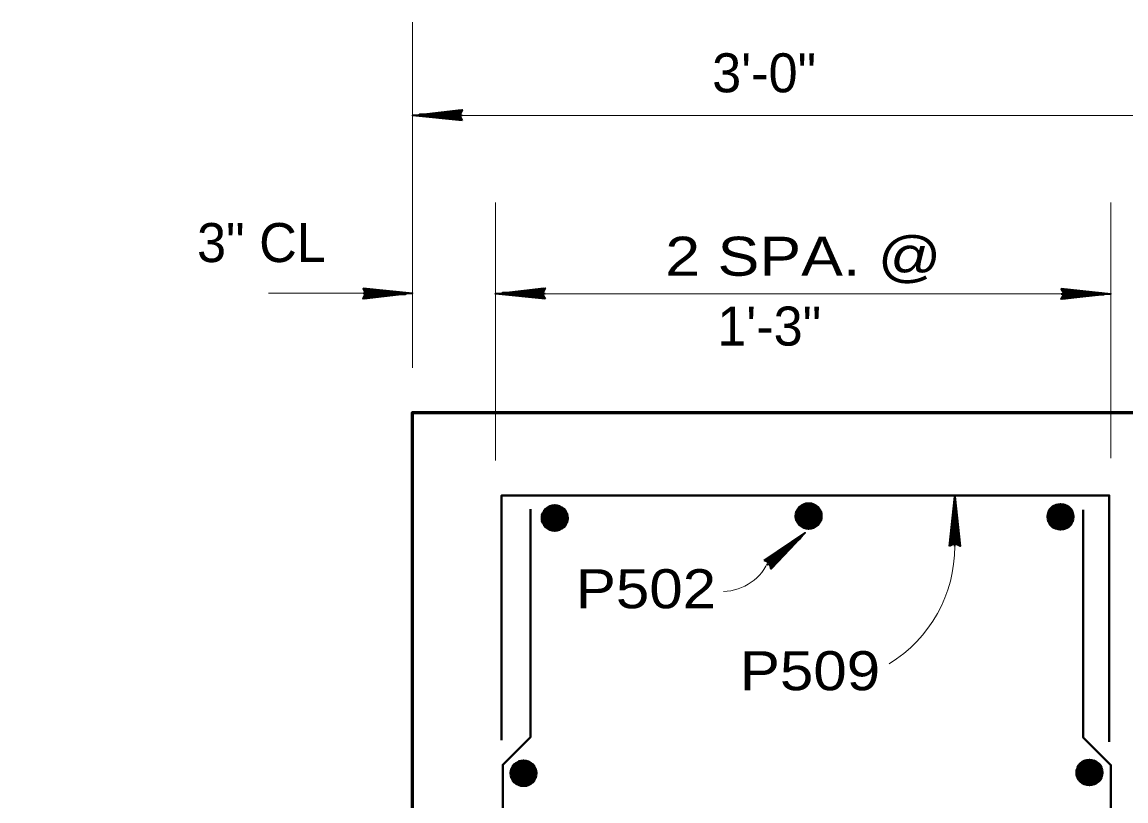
# Model space of a CAD drawing. Extents: x 3.64 to 6.84, y -0.8 to 1.19.
# Drawn here: x 5.0189 to 5.2545, y 0.1917 to 0.358 of the extents above; entities that cross this region are included whole.
import ezdxf

# ---------------------------------------------------------------- set-up
doc = ezdxf.new("R2010")
doc.units = 0
doc.header["$LTSCALE"] = 0.0033
doc.layers.add('1', color=7, linetype='Continuous', lineweight=40)

msp = doc.modelspace()

# ---------------------------------------------------------------- linework, layer by layer
at = {"layer": '1', "lineweight": 13}
for p, q in [((5.10225, 0.284167), (5.10225, 0.358)), ((5.1025, 0.338083), (5.268917, 0.338083)), ((5.119917, 0.264417), (5.119917, 0.3195)), ((5.25125, 0.264917), (5.25125, 0.3195)), ((5.0715, 0.300083), (5.092333, 0.300083)), ((5.11975, 0.3), (5.250667, 0.3))]:
    msp.add_line(p, q, dxfattribs=at)
at = {"layer": '1', "lineweight": 35}
for p, q in [((5.112833, 0.338083), (5.10225, 0.338083)), ((5.112583, 0.33725), (5.10475, 0.33825)), ((5.112583, 0.33725), (5.10475, 0.338083)), ((5.112583, 0.337083), (5.10475, 0.338)), ((5.112583, 0.337083), (5.10475, 0.338)), ((5.112583, 0.337167), (5.10475, 0.338)), ((5.112583, 0.339167), (5.10525, 0.338333)), ((5.112583, 0.339), (5.10525, 0.33825)), ((5.112583, 0.338917), (5.10525, 0.338083)), ((5.112667, 0.33875), (5.105333, 0.338)), ((5.091667, 0.300083), (5.10225, 0.300083)), ((5.091833, 0.299417), (5.099167, 0.300167)), ((5.091917, 0.301083), (5.09975, 0.300167)), ((5.091917, 0.301083), (5.09975, 0.300167)), ((5.091917, 0.301), (5.09975, 0.300167)), ((5.091917, 0.300917), (5.09975, 0.300083)), ((5.091917, 0.300917), (5.09975, 0.299917)), ((5.091917, 0.29925), (5.09925, 0.300083)), ((5.091917, 0.299167), (5.09925, 0.299917)), ((5.091917, 0.299), (5.09925, 0.299833)), ((5.1305, 0.3), (5.119917, 0.3)), ((5.13025, 0.299167), (5.122417, 0.300167)), ((5.13025, 0.299167), (5.122417, 0.3)), ((5.13025, 0.299), (5.122417, 0.299917)), ((5.13025, 0.299), (5.122417, 0.299917)), ((5.13025, 0.299083), (5.122417, 0.299917)), ((5.13025, 0.301083), (5.122917, 0.30025)), ((5.13025, 0.300917), (5.122917, 0.300167)), ((5.13025, 0.300833), (5.122917, 0.3)), ((5.130333, 0.300667), (5.123, 0.299917)), ((5.240667, 0.3), (5.25125, 0.3)), ((5.240833, 0.299333), (5.248167, 0.300083)), ((5.240917, 0.301), (5.24875, 0.300083)), ((5.240917, 0.301), (5.24875, 0.300083)), ((5.240917, 0.300917), (5.24875, 0.300083)), ((5.240917, 0.300833), (5.24875, 0.3)), ((5.240917, 0.300833), (5.24875, 0.299833)), ((5.240917, 0.299167), (5.24825, 0.3)), ((5.240917, 0.299083), (5.24825, 0.299833)), ((5.240917, 0.298917), (5.24825, 0.29975)), ((5.217917, 0.246083), (5.217917, 0.256667)), ((5.216917, 0.246333), (5.217833, 0.254167)), ((5.216917, 0.246333), (5.217833, 0.254167)), ((5.217, 0.246333), (5.217833, 0.254167)), ((5.217083, 0.246333), (5.217917, 0.254167)), ((5.217083, 0.246333), (5.218083, 0.254167)), ((5.218583, 0.24625), (5.217833, 0.253583)), ((5.21875, 0.246333), (5.217917, 0.253667)), ((5.218833, 0.246333), (5.218083, 0.253667)), ((5.219, 0.246333), (5.218167, 0.253667)), ((5.177583, 0.242917), (5.184167, 0.247417)), ((5.177583, 0.242917), (5.184167, 0.247417)), ((5.177667, 0.242917), (5.184167, 0.247417)), ((5.178, 0.242), (5.186, 0.248917)), ((5.17775, 0.242917), (5.18425, 0.24725)), ((5.17775, 0.242917), (5.18425, 0.247167)), ((5.178583, 0.24175), (5.183667, 0.246917)), ((5.17875, 0.2415), (5.183917, 0.246833)), ((5.178833, 0.241583), (5.183833, 0.247)), ((5.178917, 0.241417), (5.184, 0.246833))]:
    msp.add_line(p, q, dxfattribs=at)
at = {"layer": '1'}
for p, q in [((5.134917, 0.253333), (5.133667, 0.2545)), ((5.185083, 0.254417), (5.188917, 0.25375)), ((5.187, 0.253583), (5.188333, 0.254583)), ((5.189083, 0.25375), (5.187833, 0.254917)), ((5.24075, 0.253417), (5.242083, 0.254417)), ((5.242833, 0.253583), (5.241583, 0.25475)), ((5.1305, 0.253667), (5.135083, 0.2515)), ((5.130583, 0.25225), (5.134417, 0.2515)), ((5.130583, 0.252083), (5.134417, 0.251333)), ((5.130667, 0.252667), (5.1345, 0.252)), ((5.130667, 0.2525), (5.1345, 0.25175)), ((5.13075, 0.25325), (5.134667, 0.2525)), ((5.13075, 0.253083), (5.134667, 0.252333)), ((5.13075, 0.252833), (5.134583, 0.252083)), ((5.130833, 0.253667), (5.13475, 0.253)), ((5.130833, 0.2535), (5.13475, 0.25275)), ((5.130917, 0.254), (5.13475, 0.253333)), ((5.132833, 0.253167), (5.134167, 0.254167)), ((5.184667, 0.254083), (5.18925, 0.251917)), ((5.184667, 0.25225), (5.188583, 0.2515)), ((5.18475, 0.252667), (5.188583, 0.251917)), ((5.18475, 0.2525), (5.188583, 0.25175)), ((5.184833, 0.253083), (5.188667, 0.252417)), ((5.184833, 0.252917), (5.188667, 0.252167)), ((5.184917, 0.253667), (5.188833, 0.252917)), ((5.184917, 0.2535), (5.188833, 0.25275)), ((5.184917, 0.25325), (5.18875, 0.2525)), ((5.185, 0.254083), (5.188917, 0.253417)), ((5.185, 0.253917), (5.188917, 0.253167)), ((5.238417, 0.253917), (5.243, 0.25175)), ((5.238417, 0.252083), (5.242333, 0.251333)), ((5.2385, 0.2525), (5.242333, 0.25175)), ((5.2385, 0.252333), (5.242333, 0.251583)), ((5.238583, 0.252917), (5.242417, 0.25225)), ((5.238583, 0.25275), (5.242417, 0.252)), ((5.238667, 0.2535), (5.242583, 0.25275)), ((5.238667, 0.253333), (5.242583, 0.252583)), ((5.238667, 0.253083), (5.2425, 0.252333)), ((5.23875, 0.253917), (5.242667, 0.25325)), ((5.23875, 0.25375), (5.242667, 0.253)), ((5.238833, 0.25425), (5.242667, 0.253583)), ((5.130333, 0.250917), (5.134167, 0.250167)), ((5.130333, 0.25075), (5.134167, 0.25)), ((5.130417, 0.251417), (5.134333, 0.250667)), ((5.130417, 0.25125), (5.13425, 0.2505)), ((5.130417, 0.251), (5.13425, 0.250333)), ((5.1305, 0.251833), (5.134417, 0.251083)), ((5.134667, 0.2505), (5.130917, 0.250083)), ((5.1845, 0.251333), (5.188333, 0.250583)), ((5.1845, 0.251167), (5.188333, 0.250417)), ((5.184583, 0.251833), (5.1885, 0.251083)), ((5.184583, 0.251667), (5.188417, 0.250917)), ((5.184583, 0.251417), (5.188417, 0.25075)), ((5.188833, 0.250917), (5.185083, 0.2505)), ((5.23825, 0.251167), (5.242083, 0.250417)), ((5.23825, 0.251), (5.242083, 0.25025)), ((5.238333, 0.251667), (5.24225, 0.250917)), ((5.238333, 0.2515), (5.242167, 0.25075)), ((5.238333, 0.25125), (5.242167, 0.250583)), ((5.242583, 0.25075), (5.238833, 0.250333)), ((5.123833, 0.199167), (5.128417, 0.197)), ((5.124, 0.198167), (5.127833, 0.1975)), ((5.124, 0.198), (5.127833, 0.19725)), ((5.124083, 0.19875), (5.128, 0.198)), ((5.124083, 0.198583), (5.128, 0.197833)), ((5.124083, 0.198333), (5.127917, 0.197583)), ((5.124167, 0.199167), (5.128083, 0.1985)), ((5.124167, 0.199), (5.128083, 0.19825)), ((5.12425, 0.1995), (5.128083, 0.198833)), ((5.126167, 0.198667), (5.1275, 0.199667)), ((5.12825, 0.198833), (5.127, 0.2)), ((5.244583, 0.199333), (5.249167, 0.197167)), ((5.244667, 0.197917), (5.2485, 0.197167)), ((5.24475, 0.198333), (5.248583, 0.197667)), ((5.24475, 0.198167), (5.248583, 0.197417)), ((5.244833, 0.198917), (5.24875, 0.198167)), ((5.244833, 0.19875), (5.24875, 0.198)), ((5.244833, 0.1985), (5.248667, 0.19775)), ((5.244917, 0.199333), (5.248833, 0.198667)), ((5.244917, 0.199167), (5.248833, 0.198417)), ((5.245, 0.199667), (5.248833, 0.199)), ((5.246917, 0.198833), (5.24825, 0.199833)), ((5.249, 0.199), (5.24775, 0.200167)), ((5.123667, 0.196417), (5.1275, 0.195667)), ((5.123667, 0.19625), (5.1275, 0.1955)), ((5.12375, 0.196917), (5.127667, 0.196167)), ((5.12375, 0.19675), (5.127583, 0.196)), ((5.12375, 0.1965), (5.127583, 0.195833)), ((5.123833, 0.197333), (5.12775, 0.196583)), ((5.123917, 0.19775), (5.12775, 0.197)), ((5.123917, 0.197583), (5.12775, 0.196833)), ((5.128, 0.196), (5.12425, 0.195583)), ((5.244417, 0.196583), (5.24825, 0.195833)), ((5.244417, 0.196417), (5.24825, 0.195667)), ((5.2445, 0.197083), (5.248417, 0.196333)), ((5.2445, 0.196917), (5.248333, 0.196167)), ((5.2445, 0.196667), (5.248333, 0.196)), ((5.244583, 0.1975), (5.2485, 0.19675)), ((5.244667, 0.19775), (5.2485, 0.197)), ((5.24875, 0.196167), (5.245, 0.19575))]:
    msp.add_line(p, q, dxfattribs=at)
at = {"layer": '1', "lineweight": 60}
for p, q in [((5.13075, 0.253667), (5.130583, 0.25075)), ((5.131, 0.253667), (5.13075, 0.25075)), ((5.131167, 0.253667), (5.131, 0.250667)), ((5.131333, 0.253667), (5.131083, 0.250667)), ((5.1315, 0.253667), (5.131333, 0.250667)), ((5.13175, 0.253667), (5.131583, 0.250667)), ((5.132, 0.253667), (5.13175, 0.250667)), ((5.132083, 0.253583), (5.131917, 0.250667)), ((5.13225, 0.253583), (5.132083, 0.250667)), ((5.132417, 0.253583), (5.13225, 0.250667)), ((5.132667, 0.253583), (5.132417, 0.250667)), ((5.132833, 0.253583), (5.132667, 0.250667)), ((5.133083, 0.2535), (5.132833, 0.250583)), ((5.133333, 0.2535), (5.133083, 0.250583)), ((5.1335, 0.2535), (5.133333, 0.250583)), ((5.133583, 0.2535), (5.133417, 0.250583)), ((5.13375, 0.2535), (5.133583, 0.250583)), ((5.133833, 0.2535), (5.133667, 0.250583)), ((5.134083, 0.253417), (5.133833, 0.2505)), ((5.13425, 0.253417), (5.134083, 0.2505)), ((5.134417, 0.253417), (5.134167, 0.2505)), ((5.134583, 0.253417), (5.134417, 0.2505)), ((5.134833, 0.253417), (5.134667, 0.2505)), ((5.135083, 0.2515), (5.134917, 0.253333)), ((5.184917, 0.254083), (5.18475, 0.251167)), ((5.185167, 0.254083), (5.184917, 0.251167)), ((5.185333, 0.254083), (5.185167, 0.251083)), ((5.1855, 0.254083), (5.18525, 0.251083)), ((5.185667, 0.254083), (5.1855, 0.251083)), ((5.185917, 0.254083), (5.18575, 0.251083)), ((5.186167, 0.254083), (5.185917, 0.251083)), ((5.18625, 0.254), (5.186083, 0.251083)), ((5.186417, 0.254), (5.18625, 0.251083)), ((5.186583, 0.254), (5.186417, 0.251083)), ((5.186833, 0.254), (5.186583, 0.251083)), ((5.187, 0.254), (5.186833, 0.251083)), ((5.18725, 0.253917), (5.187, 0.251)), ((5.1875, 0.253917), (5.18725, 0.251)), ((5.187667, 0.253917), (5.1875, 0.251)), ((5.18775, 0.253917), (5.187583, 0.251)), ((5.187917, 0.253917), (5.18775, 0.251)), ((5.188, 0.253917), (5.187833, 0.251)), ((5.18825, 0.253833), (5.188, 0.250917)), ((5.188417, 0.253833), (5.18825, 0.250917)), ((5.188583, 0.253833), (5.188333, 0.250917)), ((5.18875, 0.253833), (5.188583, 0.250917)), ((5.189, 0.253833), (5.188833, 0.250917)), ((5.18925, 0.251917), (5.189083, 0.25375)), ((5.238667, 0.253917), (5.2385, 0.251)), ((5.238917, 0.253917), (5.238667, 0.251)), ((5.239083, 0.253917), (5.238917, 0.250917)), ((5.23925, 0.253917), (5.239, 0.250917)), ((5.239417, 0.253917), (5.23925, 0.250917)), ((5.239667, 0.253917), (5.2395, 0.250917)), ((5.239917, 0.253917), (5.239667, 0.250917)), ((5.24, 0.253833), (5.239833, 0.250917)), ((5.240167, 0.253833), (5.24, 0.250917)), ((5.240333, 0.253833), (5.240167, 0.250917)), ((5.240583, 0.253833), (5.240333, 0.250917)), ((5.24075, 0.253833), (5.240583, 0.250917)), ((5.241, 0.25375), (5.24075, 0.250833)), ((5.24125, 0.25375), (5.241, 0.250833)), ((5.241417, 0.25375), (5.24125, 0.250833)), ((5.2415, 0.25375), (5.241333, 0.250833)), ((5.241667, 0.25375), (5.2415, 0.250833)), ((5.24175, 0.25375), (5.241583, 0.250833)), ((5.242, 0.253667), (5.24175, 0.25075)), ((5.242167, 0.253667), (5.242, 0.25075)), ((5.242333, 0.253667), (5.242083, 0.25075)), ((5.2425, 0.253667), (5.242333, 0.25075)), ((5.24275, 0.253667), (5.242583, 0.25075)), ((5.243, 0.25175), (5.242833, 0.253583)), ((5.135083, 0.2515), (5.130333, 0.25075)), ((5.18925, 0.251917), (5.1845, 0.251167)), ((5.243, 0.25175), (5.23825, 0.251)), ((5.124083, 0.199167), (5.123917, 0.19625)), ((5.124333, 0.199167), (5.124083, 0.19625)), ((5.1245, 0.199167), (5.124333, 0.196167)), ((5.124667, 0.199167), (5.124417, 0.196167)), ((5.124833, 0.199167), (5.124667, 0.196167)), ((5.125083, 0.199167), (5.124917, 0.196167)), ((5.125333, 0.199167), (5.125083, 0.196167)), ((5.125417, 0.199083), (5.12525, 0.196167)), ((5.125583, 0.199083), (5.125417, 0.196167)), ((5.12575, 0.199083), (5.125583, 0.196167)), ((5.126, 0.199083), (5.12575, 0.196167)), ((5.126167, 0.199083), (5.126, 0.196167)), ((5.126417, 0.199), (5.126167, 0.196083)), ((5.126667, 0.199), (5.126417, 0.196083)), ((5.126833, 0.199), (5.126667, 0.196083)), ((5.126917, 0.199), (5.12675, 0.196083)), ((5.127083, 0.199), (5.126917, 0.196083)), ((5.127167, 0.199), (5.127, 0.196083)), ((5.127417, 0.198917), (5.127167, 0.196)), ((5.127583, 0.198917), (5.127417, 0.196)), ((5.12775, 0.198917), (5.1275, 0.196)), ((5.127917, 0.198917), (5.12775, 0.196)), ((5.128167, 0.198917), (5.128, 0.196)), ((5.128417, 0.197), (5.12825, 0.198833)), ((5.244833, 0.199333), (5.244667, 0.196417)), ((5.245083, 0.199333), (5.244833, 0.196417)), ((5.24525, 0.199333), (5.245083, 0.196333)), ((5.245417, 0.199333), (5.245167, 0.196333)), ((5.245583, 0.199333), (5.245417, 0.196333)), ((5.245833, 0.199333), (5.245667, 0.196333)), ((5.246083, 0.199333), (5.245833, 0.196333)), ((5.246167, 0.19925), (5.246, 0.196333)), ((5.246333, 0.19925), (5.246167, 0.196333)), ((5.2465, 0.19925), (5.246333, 0.196333)), ((5.24675, 0.19925), (5.2465, 0.196333)), ((5.246917, 0.19925), (5.24675, 0.196333)), ((5.247167, 0.199167), (5.246917, 0.19625)), ((5.247417, 0.199167), (5.247167, 0.19625)), ((5.247583, 0.199167), (5.247417, 0.19625)), ((5.247667, 0.199167), (5.2475, 0.19625)), ((5.247833, 0.199167), (5.247667, 0.19625)), ((5.247917, 0.199167), (5.24775, 0.19625)), ((5.248167, 0.199083), (5.247917, 0.196167)), ((5.248333, 0.199083), (5.248167, 0.196167)), ((5.2485, 0.199083), (5.24825, 0.196167)), ((5.248667, 0.199083), (5.2485, 0.196167)), ((5.248917, 0.199083), (5.24875, 0.196167)), ((5.249167, 0.197167), (5.249, 0.199)), ((5.128417, 0.197), (5.123667, 0.19625)), ((5.249167, 0.197167), (5.244417, 0.196417))]:
    msp.add_line(p, q, dxfattribs=at)
at = {"layer": '1', "lineweight": 35}
for points in [[(5.112833, 0.337), (5.10225, 0.338083), (5.112833, 0.33925), (5.11225, 0.338083)], [(5.112083, 0.338), (5.107417, 0.337917), (5.107417, 0.338), (5.108333, 0.338), (5.112083, 0.337917), (5.109083, 0.337833), (5.11225, 0.33775), (5.11, 0.337667), (5.11225, 0.337583), (5.10875, 0.337833), (5.104083, 0.338), (5.105, 0.33825), (5.10375, 0.33825), (5.112083, 0.33825), (5.109667, 0.338417), (5.11225, 0.338417), (5.106917, 0.338), (5.11225, 0.338667)], [(5.091667, 0.301167), (5.10225, 0.300083), (5.091667, 0.298917), (5.09225, 0.300083)], [(5.092417, 0.300167), (5.097083, 0.30025), (5.097083, 0.300167), (5.096167, 0.300167), (5.092417, 0.30025), (5.095417, 0.300333), (5.09225, 0.300417), (5.0945, 0.3005), (5.09225, 0.300583), (5.09575, 0.300333), (5.100417, 0.300167), (5.0995, 0.299917), (5.10075, 0.299917), (5.092417, 0.299917), (5.094833, 0.29975), (5.09225, 0.29975), (5.097583, 0.300167), (5.09225, 0.2995)], [(5.1305, 0.298917), (5.119917, 0.3), (5.1305, 0.301167), (5.129917, 0.3)], [(5.12975, 0.299917), (5.125083, 0.299833), (5.125083, 0.299917), (5.126, 0.299917), (5.12975, 0.299833), (5.12675, 0.29975), (5.129917, 0.299667), (5.127667, 0.299583), (5.129917, 0.2995), (5.126417, 0.29975), (5.12175, 0.299917), (5.122667, 0.300167), (5.121417, 0.300167), (5.12975, 0.300167), (5.127333, 0.300333), (5.129917, 0.300333), (5.124583, 0.299917), (5.129917, 0.300583)], [(5.240667, 0.301083), (5.25125, 0.3), (5.240667, 0.298833), (5.24125, 0.3)], [(5.241417, 0.300083), (5.246083, 0.300167), (5.246083, 0.300083), (5.245167, 0.300083), (5.241417, 0.300167), (5.244417, 0.30025), (5.24125, 0.300333), (5.2435, 0.300417), (5.24125, 0.3005), (5.24475, 0.30025), (5.249417, 0.300083), (5.2485, 0.299833), (5.24975, 0.299833), (5.241417, 0.299833), (5.243833, 0.299667), (5.24125, 0.299667), (5.246583, 0.300083), (5.24125, 0.299417)], [(5.216833, 0.246083), (5.217917, 0.256667), (5.219083, 0.246083), (5.217917, 0.246667)], [(5.217833, 0.246833), (5.21775, 0.2515), (5.217833, 0.2515), (5.217833, 0.250583), (5.21775, 0.246833), (5.217667, 0.249833), (5.217583, 0.246667), (5.2175, 0.248917), (5.217417, 0.246667), (5.217667, 0.250167), (5.217833, 0.254833), (5.218083, 0.253917), (5.218083, 0.255167), (5.218083, 0.246833), (5.21825, 0.24925), (5.21825, 0.246667), (5.217833, 0.252), (5.2185, 0.246667)], [(5.17725, 0.243), (5.186, 0.248917), (5.17875, 0.24125), (5.178417, 0.2425)], [(5.178583, 0.242583), (5.182167, 0.24575), (5.18225, 0.245667), (5.181417, 0.245083), (5.1785, 0.242583), (5.18075, 0.24475), (5.178333, 0.242833), (5.179917, 0.24425), (5.178167, 0.242833), (5.181, 0.245), (5.184667, 0.247917), (5.184083, 0.247), (5.185, 0.247833), (5.17875, 0.2425), (5.180667, 0.243917), (5.178667, 0.242167), (5.182417, 0.245917), (5.178917, 0.242)]]:
    msp.add_lwpolyline(points, close=True, dxfattribs=at)
for points in [[(5.112083, 0.338), (5.1125, 0.33725), (5.11225, 0.3375), (5.112083, 0.337833), (5.111833, 0.33775), (5.112, 0.337417), (5.112167, 0.338167), (5.112333, 0.338667), (5.112583, 0.339083)], [(5.092417, 0.300167), (5.092, 0.300917), (5.09225, 0.300667), (5.092417, 0.300333), (5.092667, 0.300417), (5.0925, 0.30075), (5.092333, 0.3), (5.092167, 0.2995), (5.091917, 0.299083)], [(5.12975, 0.299917), (5.130167, 0.299167), (5.129917, 0.299417), (5.12975, 0.29975), (5.1295, 0.299667), (5.129667, 0.299333), (5.129833, 0.300083), (5.13, 0.300583), (5.13025, 0.301)], [(5.241417, 0.300083), (5.241, 0.300833), (5.24125, 0.300583), (5.241417, 0.30025), (5.241667, 0.300333), (5.2415, 0.300667), (5.241333, 0.299917), (5.241167, 0.299417), (5.240917, 0.299)], [(5.217833, 0.246833), (5.217083, 0.246417), (5.217333, 0.246667), (5.217667, 0.246833), (5.217583, 0.247083), (5.21725, 0.246917), (5.218, 0.24675), (5.2185, 0.246583), (5.218917, 0.246333)], [(5.178583, 0.242583), (5.177833, 0.243), (5.178083, 0.242833), (5.178417, 0.242833), (5.178583, 0.243), (5.178167, 0.243083), (5.178667, 0.2425), (5.17875, 0.242083), (5.178833, 0.241417)]]:
    msp.add_lwpolyline(points, dxfattribs=at)
at = {"layer": '1', "lineweight": 60}
for points in [[(5.018917, -0.058667), (5.10225, -0.058667), (5.10225, 0.274667), (5.268917, 0.274667), (5.268917, -0.058667), (5.35225, -0.058667)], [(5.134167, 0.25), (5.134167, 0.254167), (5.1325, 0.2495), (5.133, 0.254667), (5.130917, 0.250083), (5.131667, 0.254583), (5.13325, 0.249583), (5.130083, 0.252917), (5.134917, 0.253333), (5.131667, 0.249667), (5.133667, 0.2545), (5.1305, 0.253667), (5.130333, 0.25075)], [(5.130917, 0.250083), (5.132417, 0.252333), (5.13025, 0.25325), (5.13225, 0.254667), (5.132417, 0.252417), (5.134083, 0.250083), (5.130083, 0.252417), (5.132833, 0.253167)], [(5.133667, 0.2545), (5.132417, 0.252333), (5.134667, 0.2505)], [(5.188333, 0.250417), (5.188333, 0.254583), (5.186667, 0.249917), (5.187167, 0.255083), (5.185083, 0.2505), (5.185833, 0.255), (5.187417, 0.25), (5.18425, 0.253333), (5.189083, 0.25375), (5.185833, 0.250083), (5.187833, 0.254917), (5.184667, 0.254083), (5.1845, 0.251167)], [(5.185083, 0.2505), (5.186583, 0.25275), (5.184417, 0.253667), (5.186417, 0.255083), (5.186583, 0.252833), (5.18825, 0.2505), (5.18425, 0.252833), (5.187, 0.253583)], [(5.187833, 0.254917), (5.186583, 0.25275), (5.188833, 0.250917)], [(5.242083, 0.25025), (5.242083, 0.254417), (5.240417, 0.24975), (5.240917, 0.254917), (5.238833, 0.250333), (5.239583, 0.254833), (5.241167, 0.249833), (5.238, 0.253167), (5.242833, 0.253583), (5.239583, 0.249917), (5.241583, 0.25475), (5.238417, 0.253917), (5.23825, 0.251)], [(5.238833, 0.250333), (5.240333, 0.252583), (5.238167, 0.2535), (5.240167, 0.254917), (5.240333, 0.252667), (5.242, 0.250333), (5.238, 0.252667), (5.24075, 0.253417)], [(5.241583, 0.25475), (5.240333, 0.252583), (5.242583, 0.25075)], [(5.129917, 0.252), (5.135083, 0.252667), (5.1305, 0.253667)], [(5.184083, 0.252417), (5.18925, 0.253083), (5.184667, 0.254083)], [(5.237833, 0.25225), (5.243, 0.252917), (5.238417, 0.253917)], [(5.24825, 0.195667), (5.24825, 0.199833), (5.246583, 0.195167), (5.247083, 0.200333), (5.245, 0.19575), (5.24575, 0.20025), (5.247333, 0.19525), (5.244167, 0.198583), (5.249, 0.199), (5.24575, 0.195333), (5.24775, 0.200167), (5.244583, 0.199333), (5.244417, 0.196417)], [(5.245, 0.19575), (5.2465, 0.198), (5.244333, 0.198917), (5.246333, 0.200333), (5.2465, 0.198083), (5.248167, 0.19575), (5.244167, 0.198083), (5.246917, 0.198833)], [(5.12325, 0.1975), (5.128417, 0.198167), (5.123833, 0.199167)], [(5.1275, 0.1955), (5.1275, 0.199667), (5.125833, 0.195), (5.126333, 0.200167), (5.12425, 0.195583), (5.125, 0.200083), (5.126583, 0.195083), (5.123417, 0.198417), (5.12825, 0.198833), (5.125, 0.195167), (5.127, 0.2), (5.123833, 0.199167), (5.123667, 0.19625)], [(5.12425, 0.195583), (5.12575, 0.197833), (5.123583, 0.19875), (5.125583, 0.200167), (5.12575, 0.197917), (5.127417, 0.195583), (5.123417, 0.197917), (5.126167, 0.198667)], [(5.127, 0.2), (5.12575, 0.197833), (5.128, 0.196)], [(5.244, 0.197667), (5.249167, 0.198333), (5.244583, 0.199333)], [(5.24775, 0.200167), (5.2465, 0.198), (5.24875, 0.196167)]]:
    msp.add_lwpolyline(points, dxfattribs=at)
at = {"layer": '1'}
for points in [[(5.12125, 0.204667), (5.12125, 0.256917), (5.250917, 0.256917), (5.250917, 0.204333)], [(5.127417, 0.254), (5.127417, 0.205333), (5.1215, 0.199417), (5.1215, -0.008917), (5.127417, -0.014833), (5.127417, -0.04725)], [(5.245333, -0.044), (5.245333, -0.014917), (5.25125, -0.009), (5.25125, 0.199333), (5.245333, 0.20525), (5.245333, 0.253833)], [(5.130333, 0.25075), (5.132417, 0.2495), (5.134167, 0.25), (5.135083, 0.2515)], [(5.1845, 0.251167), (5.186583, 0.249917), (5.188333, 0.250417), (5.18925, 0.251917)], [(5.23825, 0.251), (5.240333, 0.24975), (5.242083, 0.25025), (5.243, 0.25175)], [(5.123667, 0.19625), (5.12575, 0.195), (5.1275, 0.1955), (5.128417, 0.197)], [(5.244417, 0.196417), (5.2465, 0.195167), (5.24825, 0.195667), (5.249167, 0.197167)]]:
    msp.add_lwpolyline(points, dxfattribs=at)
at = {"layer": '1', "lineweight": 60}
for centre in [(5.132583, 0.2521), (5.18675, 0.252517), (5.2405, 0.25235), (5.125917, 0.1976), (5.246667, 0.197767)]:
    msp.add_circle(centre, 0.00264, dxfattribs=at)
at = {"layer": '1', "lineweight": 13}
for centre, radius, start, end in [((5.188909, 0.245825), 0.029009, 301.15475, 0.51002), ((5.168269, 0.247237), 0.010825, 271.66343, 338.38632)]:
    msp.add_arc(centre, radius, start, end, dxfattribs=at)

# ---------------------------------------------------------------- texts
at = {"layer": '1'}
for s, height, p in [('3\'-0"', 0.008333, (5.166167, 0.343)), ('3" CL', 0.008334, (5.05625, 0.30675)), ('1\'-3"', 0.008334, (5.16725, 0.288917))]:
    msp.add_text(s, height=height, dxfattribs=at).set_placement(p)
for s, height, width, p in [('2 SPA. @ ', 0.008334, 1.2, (5.156167, 0.303833)), ('P502', 0.008333, 1.15, (5.137083, 0.232833)), ('P509', 0.008334, 1.15, (5.172083, 0.215333))]:
    msp.add_text(s, height=height, dxfattribs=dict(at, width=width)).set_placement(p)

doc.saveas('drawing.dxf')
